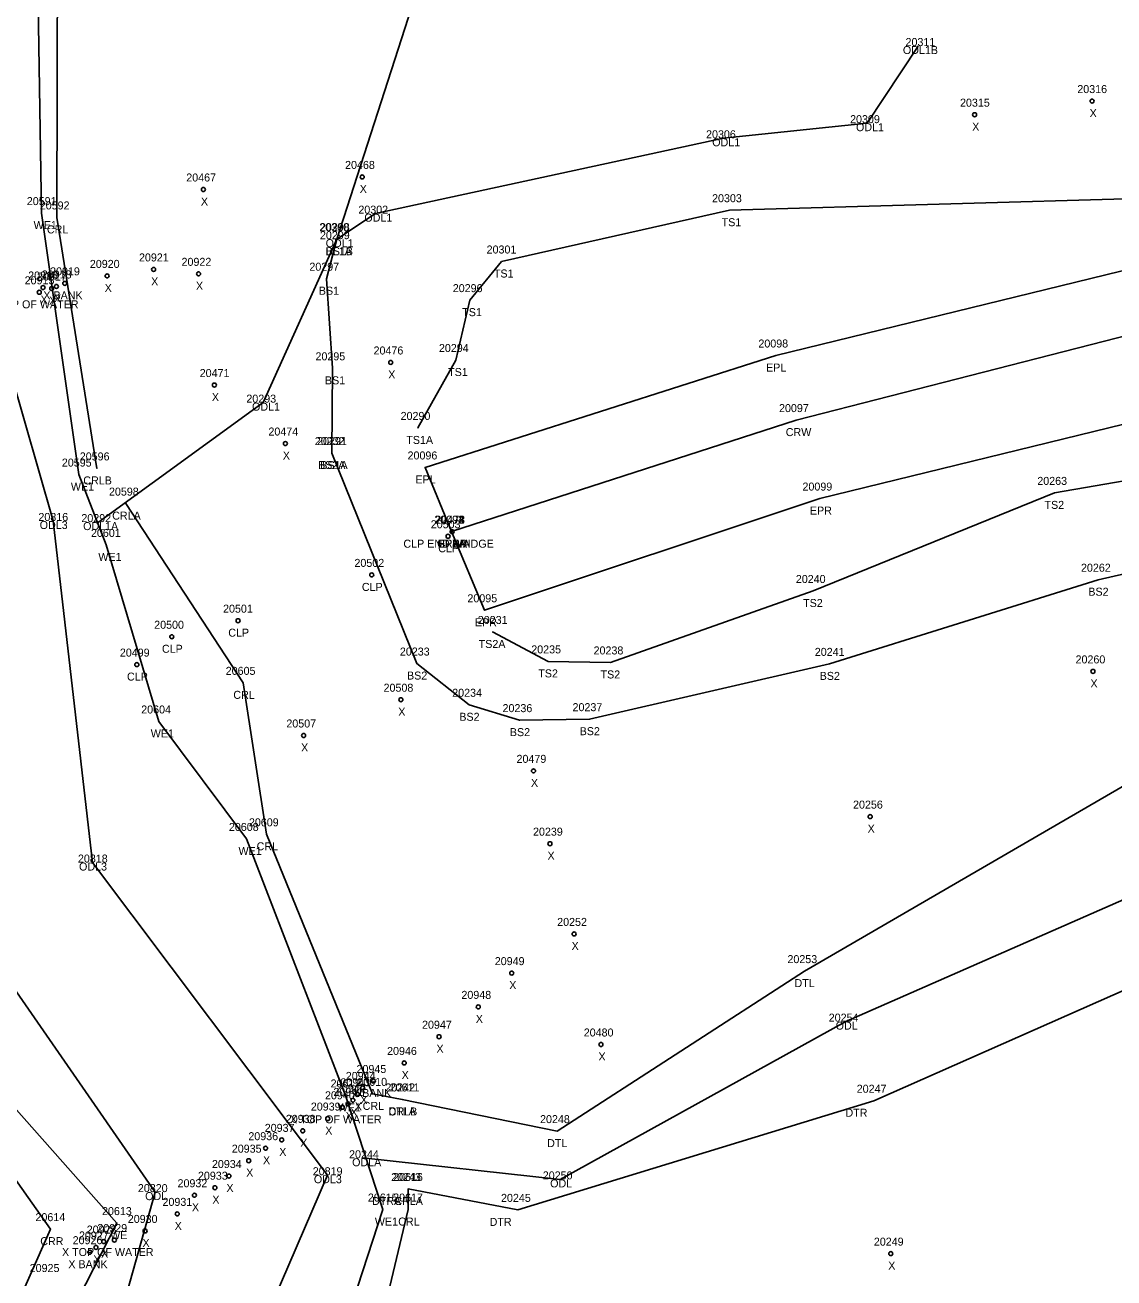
# Model space of a CAD drawing. Extents: x 1966740 to 1969291, y 1117378 to 1118461.
# Drawn here: x 1967825.7 to 1967961.8, y 1117802.2 to 1117958.8 of the extents above; entities that cross this region are included whole.
import ezdxf

# ---------------------------------------------------------------- set-up
doc = ezdxf.new("R2010")
doc.units = 0
for name, color, linetype in [('RD_DTM_BkLn1', 7, 'Continuous'), ('RD_DTM_BkLn2', 7, 'Continuous'), ('RD_EX_H2O', 7, 'Continuous'), ('RD_EX_H2O_txCode', 7, 'Continuous'), ('RD_EX_Road', 7, 'Continuous'), ('RD_EX_Road_txCode', 7, 'Continuous'), ('RD_SMD_Locator', 7, 'Continuous'), ('RD_SMD_Misc', 7, 'Continuous')]:
    doc.layers.add(name, color=color, linetype=linetype)

msp = doc.modelspace()

# ---------------------------------------------------------------- linework, layer by layer
at = {"layer": 'RD_DTM_BkLn1'}
for points in [[(1967864.65, 1117932.01), (1967874.44, 1117962.38), (1967900.7, 1118004.22), (1967938.17, 1118014.53)], [(1967878.98, 1117895.46), (1967922.07, 1117909.4), (1967968.89, 1117921.38), (1968013.49, 1117926.44), (1968059.29, 1117929.05), (1968105.63, 1117929.86), (1968159.12, 1117928.97), (1968212.65, 1117927.25), (1968318.5, 1117923.95), (1968422.42, 1117919.39), (1968529.36, 1117916.3)]]:
    msp.add_lwpolyline(points, dxfattribs=at)
at = {"layer": 'RD_DTM_BkLn2'}
for points in [[(1967874.77, 1117908.42), (1967879.51, 1117916.91), (1967881.27, 1117924.39), (1967885.24, 1117929.22), (1967913.7, 1117935.63), (1967966.11, 1117937.12), (1968012.39, 1117940.75), (1968059.42, 1117941.87), (1968105.44, 1117943.27), (1968158.32, 1117942.95), (1968212.48, 1117942.1), (1968371.25, 1117933.41), (1968422.85, 1117933.68), (1968531.49, 1117931.42)], [(1967864, 1117905.28), (1967864.09, 1117915.87), (1967863.33, 1117927.07), (1967864.65, 1117932.01)], [(1967884.1, 1117882.92), (1967891.06, 1117879.24), (1967898.84, 1117879.11), (1967924.17, 1117888.04), (1967954.33, 1117900.3), (1967970.81, 1117903.15), (1968012.93, 1117910.83), (1968059.62, 1117915.05), (1968105.25, 1117916.2), (1968157.57, 1117912.09), (1968210.74, 1117910.77), (1968320.32, 1117907.54), (1968423.18, 1117904.83), (1968528.99, 1117899.6)], [(1967864, 1117905.28), (1967874.64, 1117878.97), (1967881.18, 1117873.82), (1967887.49, 1117871.9), (1967896.22, 1117872.02), (1967926.22, 1117878.93), (1967959.79, 1117889.45), (1967973.08, 1117892.46), (1968014.67, 1117899.65), (1968058.49, 1117903.84)]]:
    msp.add_lwpolyline(points, dxfattribs=at)
at = {"layer": 'RD_EX_H2O'}
for points in [[(1967852.4, 1118390.04), (1967912.21, 1118383.64), (1967925.08, 1118336.82), (1967944.14, 1118294.4), (1967946.67, 1118243.15), (1967961.58, 1118191.28), (1967922.84, 1118148.62), (1967880.18, 1118117.11), (1967858.72, 1118073.64), (1967843.96, 1118030.69), (1967829.77, 1117984.65), (1967829.63, 1117934.73), (1967834.65, 1117903.36)], [(1967852.05, 1118385.41), (1967898.77, 1118376.41), (1967924.08, 1118337.23), (1967939.81, 1118294.93), (1967943.5, 1118242.16), (1967952.29, 1118191.75), (1967920.83, 1118149.81), (1967879.07, 1118118.61), (1967857.7, 1118074.04), (1967841.84, 1118031.93), (1967826.93, 1117984.9), (1967827.73, 1117935.27), (1967832.39, 1117902.59), (1967835.81, 1117893.8), (1967842.37, 1117871.73), (1967853.33, 1117857.05), (1967865.72, 1117824.99), (1967870.38, 1117810.73), (1967864.06, 1117791.33)], [(1967848.72, 1118350.07), (1967881.79, 1118342.06), (1967895.58, 1118338.92), (1967907.43, 1118282.36), (1967910.66, 1118232.56), (1967917.99, 1118192.64), (1967910.91, 1118176.45), (1967849.83, 1118135.18), (1967825.91, 1118086.77), (1967802.99, 1118041.98), (1967795.15, 1117992.28), (1967793.27, 1117935.35), (1967800.64, 1117889.8), (1967800.4, 1117872.52), (1967800.8, 1117854.99), (1967811.67, 1117837.73), (1967837.15, 1117809.04), (1967808.01, 1117752.12)], [(1967837.87, 1118086.59), (1967816.35, 1118042.52), (1967807.65, 1118000.54), (1967802.25, 1117964.95), (1967802.7, 1117929.05), (1967808.24, 1117891.66), (1967818.1, 1117847.27), (1967841.92, 1117812.91), (1967830.83, 1117773.47), (1967807.55, 1117730.13), (1967792.1, 1117688.21), (1967759.2, 1117626.42), (1967746.8, 1117597.58), (1967728.31, 1117575.82), (1967748.97, 1117519.79), (1967787.59, 1117491.86), (1967802.7, 1117484.72), (1967813.63, 1117479.24)], [(1967846.86, 1118079.71), (1967831.29, 1118034.88), (1967818.84, 1117997.76), (1967815.72, 1117964.67), (1967820.18, 1117928.06), (1967829.19, 1117896.79), (1967834.11, 1117854.1), (1967863.47, 1117815.02), (1967842.32, 1117765.95), (1967826.02, 1117725.1), (1967807.77, 1117682.35), (1967775.42, 1117611.81), (1967754.74, 1117587.12), (1967745.94, 1117565.65), (1967761.23, 1117525.28), (1967787.1, 1117502.15), (1967805.18, 1117494.11), (1967821.41, 1117490.36)], [(1967834.83, 1117896.65), (1967855.45, 1117911.58), (1967864.65, 1117932.01), (1967869.49, 1117935.2), (1967912.97, 1117944.62), (1967930.94, 1117946.51), (1967937.28, 1117956.15)], [(1967872.82, 1117824.49), (1967892.16, 1117820.53), (1967923.08, 1117840.53), (1967966.02, 1117865.44), (1967979.17, 1117870.44), (1968016.32, 1117890.41), (1968058.49, 1117903.84)], [(1967868.28, 1117817.14), (1967892.54, 1117814.5), (1967928.24, 1117834.22), (1967973.92, 1117854.29), (1967982.67, 1117861.15), (1968021.78, 1117883.3), (1968056.97, 1117897.44), (1968105.42, 1117898.77), (1968155.9, 1117899.84), (1968209.66, 1117898.76), (1968320.81, 1117895.57), (1968371.06, 1117895.25)], [(1967838.28, 1117898.96), (1967852.93, 1117876.56), (1967855.83, 1117857.63), (1967869.1, 1117825.19), (1967872.82, 1117824.49)], [(1967873.55, 1117813.3), (1967887.27, 1117810.69), (1967931.74, 1117824.33), (1967977.85, 1117844.69), (1967988.67, 1117850.69), (1968023.3, 1117871.08), (1968058.02, 1117883.74)], [(1967794.3, 1117875.45), (1967796.63, 1117853.43), (1967809.67, 1117835.4), (1967828.83, 1117808.28), (1967805.08, 1117754.56), (1967786.33, 1117708.04), (1967780.19, 1117689.35), (1967762.68, 1117651.19), (1967736.39, 1117616.3), (1967727.33, 1117611.21), (1967715.04, 1117573.35), (1967731.01, 1117514.73), (1967775.86, 1117468.11), (1967793.29, 1117458.88), (1967816.39, 1117454.18)], [(1967873.55, 1117813.3), (1967873.54, 1117810.73), (1967868.98, 1117791.48), (1967856.29, 1117756.05), (1967834.78, 1117721.72), (1967815.36, 1117678.52), (1967799.96, 1117628.39), (1967778.25, 1117587.63), (1967771.33, 1117582.11), (1967756.46, 1117564.6), (1967764.36, 1117543.85), (1967795.97, 1117517.33), (1967805.92, 1117513.21), (1967828.95, 1117503.56)]]:
    msp.add_lwpolyline(points, dxfattribs=at)
at = {"layer": 'RD_EX_Road'}
for points in [[(1967878.98, 1117895.46), (1967875.66, 1117903.48), (1967919.49, 1117917.47), (1967966.4, 1117928.95), (1968012.66, 1117935.42), (1968058.94, 1117938.37), (1968105.99, 1117939.39), (1968158.7, 1117938.56), (1968212.05, 1117937.21), (1968318.79, 1117933.28), (1968422.76, 1117929.93), (1968530.54, 1117925.7)], [(1967878.98, 1117895.46), (1967883.11, 1117885.63), (1967924.99, 1117899.59), (1967970.68, 1117910.78), (1968014.42, 1117916.56), (1968059.13, 1117919.49), (1968105.39, 1117920.31), (1968159.16, 1117919.37), (1968212.5, 1117917.97), (1968317.55, 1117914.44), (1968421.52, 1117910.75), (1968527.82, 1117906.41)]]:
    msp.add_lwpolyline(points, dxfattribs=at)
at = {"layer": 'RD_SMD_Locator'}
for centre, radius in [((1967937.28, 1117956.15), 0.001), ((1967959.04, 1117949.27), 0.25), ((1967944.36, 1117947.57), 0.25), ((1967930.94, 1117946.51), 0.001), ((1967912.97, 1117944.62), 0.001), ((1967867.81, 1117939.79), 0.25), ((1967847.96, 1117938.22), 0.25), ((1967827.73, 1117935.27), 0.001), ((1967829.63, 1117934.73), 0.001), ((1967869.49, 1117935.2), 0.001), ((1967913.7, 1117935.63), 0.001), ((1967864.65, 1117932.01), 0.001), ((1967864.65, 1117932.01), 0.001), ((1967864.65, 1117932.01), 0.001), ((1967841.74, 1117928.23), 0.25), ((1967885.24, 1117929.22), 0.001), ((1967830.64, 1117926.49), 0.25), ((1967835.93, 1117927.42), 0.25), ((1967847.35, 1117927.68), 0.25), ((1967863.33, 1117927.07), 0.001), ((1967827.45, 1117925.37), 0.25), ((1967827.92, 1117925.97), 0.25), ((1967829, 1117925.84), 0.25), ((1967829.59, 1117926.1), 0.25), ((1967881.27, 1117924.39), 0.001), ((1967919.49, 1117917.47), 0.001), ((1967864.09, 1117915.87), 0.001), ((1967871.37, 1117916.6), 0.25), ((1967879.51, 1117916.91), 0.001), ((1967849.33, 1117913.78), 0.25), ((1967855.45, 1117911.58), 0.001), ((1967922.07, 1117909.4), 0.001), ((1967874.77, 1117908.42), 0.001), ((1967858.21, 1117906.47), 0.25), ((1967864, 1117905.28), 0.001), ((1967864, 1117905.28), 0.001), ((1967834.65, 1117903.36), 0.001), ((1967875.66, 1117903.48), 0.001), ((1967832.39, 1117902.59), 0.001), ((1967954.33, 1117900.3), 0.001), ((1967838.28, 1117898.96), 0.001), ((1967924.99, 1117899.59), 0.001), ((1967829.19, 1117896.79), 0.001), ((1967834.83, 1117896.65), 0.001), ((1967878.54, 1117894.88), 0.25), ((1967879.05, 1117895.45), 0.25), ((1967878.98, 1117895.46), 0.001), ((1967878.98, 1117895.46), 0.001), ((1967878.98, 1117895.46), 0.001), ((1967835.81, 1117893.8), 0.001), ((1967869, 1117890.05), 0.25), ((1967959.79, 1117889.45), 0.001), ((1967924.17, 1117888.04), 0.001), ((1967852.29, 1117884.33), 0.25), ((1967883.11, 1117885.63), 0.001), ((1967884.1, 1117882.92), 0.001), ((1967844.01, 1117882.32), 0.25), ((1967839.64, 1117878.84), 0.25), ((1967874.64, 1117878.97), 0.001), ((1967891.06, 1117879.24), 0.001), ((1967898.84, 1117879.11), 0.001), ((1967926.22, 1117878.93), 0.001), ((1967959.15, 1117877.99), 0.25), ((1967852.93, 1117876.56), 0.001), ((1967872.64, 1117874.45), 0.25), ((1967881.18, 1117873.82), 0.001), ((1967842.37, 1117871.73), 0.001), ((1967887.49, 1117871.9), 0.001), ((1967896.22, 1117872.02), 0.001), ((1967860.49, 1117869.98), 0.25), ((1967889.22, 1117865.56), 0.25), ((1967931.3, 1117859.84), 0.25), ((1967855.83, 1117857.63), 0.001), ((1967853.33, 1117857.05), 0.001), ((1967891.28, 1117856.46), 0.25), ((1967834.11, 1117854.1), 0.001), ((1967894.3, 1117845.18), 0.25), ((1967886.5, 1117840.28), 0.25), ((1967923.08, 1117840.53), 0.001), ((1967882.32, 1117836.06), 0.25), ((1967928.24, 1117834.22), 0.001), ((1967877.41, 1117832.33), 0.25), ((1967897.65, 1117831.36), 0.25), ((1967873.06, 1117829.05), 0.25), ((1967869.21, 1117826.8), 0.25), ((1967865.72, 1117824.99), 0.001), ((1967867.2, 1117825.13), 0.25), ((1967867.88, 1117825.93), 0.25), ((1967869.1, 1117825.19), 0.001), ((1967865.32, 1117823.51), 0.25), ((1967866.04, 1117823.93), 0.25), ((1967866.64, 1117824.4), 0.25), ((1967872.82, 1117824.49), 0.001), ((1967872.82, 1117824.49), 0.001), ((1967931.74, 1117824.33), 0.001), ((1967863.5, 1117822.1), 0.25), ((1967860.38, 1117820.57), 0.25), ((1967892.16, 1117820.53), 0.001), ((1967855.73, 1117818.4), 0.25), ((1967857.75, 1117819.44), 0.25), ((1967853.62, 1117816.84), 0.25), ((1967868.28, 1117817.14), 0.001), ((1967849.4, 1117813.46), 0.25), ((1967851.15, 1117814.92), 0.25), ((1967863.47, 1117815.02), 0.001), ((1967892.54, 1117814.5), 0.001), ((1967841.92, 1117812.91), 0.001), ((1967846.84, 1117812.52), 0.25), ((1967873.55, 1117813.3), 0.001), ((1967873.55, 1117813.3), 0.001), ((1967870.38, 1117810.73), 0.001), ((1967873.54, 1117810.73), 0.001), ((1967887.27, 1117810.69), 0.001), ((1967837.15, 1117809.04), 0.001), ((1967844.69, 1117810.19), 0.25), ((1967828.83, 1117808.28), 0.001), ((1967840.67, 1117808.06), 0.25), ((1967834.53, 1117805.99), 0.25), ((1967835.5, 1117806.73), 0.25), ((1967836.83, 1117806.92), 0.25), ((1967833.76, 1117805.4), 0.25), ((1967933.88, 1117805.22), 0.25)]:
    msp.add_circle(centre, radius, dxfattribs=at)

# ---------------------------------------------------------------- texts
at = {"layer": 'RD_EX_H2O_txCode'}
for s, p in [('20311', (1967935.72, 1117956.15)), ('ODL1B', (1967935.39, 1117955.15)), ('20309', (1967928.79, 1117946.51)), ('20306', (1967910.79, 1117944.62)), ('ODL1', (1967929.53, 1117945.51)), ('ODL1', (1967911.56, 1117943.62)), ('20591', (1967825.89, 1117936.27)), ('20592', (1967827.51, 1117935.73)), ('20302', (1967867.33, 1117935.2)), ('ODL1', (1967868.08, 1117934.2)), ('WE1', (1967826.74, 1117933.27)), ('CRL', (1967828.4, 1117932.73)), ('20299', (1967862.53, 1117932.01)), ('ODL1', (1967863.24, 1117931.01)), ('20293', (1967853.33, 1117911.58)), ('ODL1', (1967854.04, 1117910.58)), ('20595', (1967830.27, 1117903.59)), ('20596', (1967832.51, 1117904.36)), ('WE1', (1967831.4, 1117900.59)), ('CRLB', (1967832.95, 1117901.36)), ('20598', (1967836.16, 1117899.96)), ('20816', (1967827.34, 1117896.79)), ('ODL3', (1967827.5, 1117895.79)), ('20292', (1967832.71, 1117896.65)), ('CRLA', (1967836.56, 1117896.96)), ('ODL1A', (1967832.93, 1117895.65)), ('20601', (1967833.91, 1117894.8)), ('WE1', (1967834.83, 1117891.8)), ('20605', (1967850.75, 1117877.56)), ('CRL', (1967851.7, 1117874.56)), ('20604', (1967840.19, 1117872.73)), ('WE1', (1967841.38, 1117869.73)), ('20609', (1967853.65, 1117858.63)), ('20608', (1967851.15, 1117858.05)), ('WE1', (1967852.35, 1117855.05)), ('CRL', (1967854.61, 1117855.63)), ('20818', (1967832.28, 1117854.1)), ('ODL3', (1967832.42, 1117853.1)), ('20253', (1967920.96, 1117841.53)), ('DTL', (1967921.84, 1117838.53)), ('20254', (1967926.12, 1117834.22)), ('ODL', (1967926.99, 1117833.22)), ('20612', (1967863.86, 1117825.99)), ('20610', (1967867.2, 1117826.19)), ('20242', (1967870.7, 1117825.49)), ('20611', (1967871.25, 1117825.49)), ('20247', (1967929.62, 1117825.33)), ('WE1', (1967864.74, 1117822.99)), ('CRL', (1967867.87, 1117823.19)), ('CRLB', (1967871.12, 1117822.49)), ('DTLA', (1967871.09, 1117822.49)), ('DTR', (1967928.21, 1117822.33)), ('20248', (1967890.04, 1117821.53)), ('DTL', (1967890.92, 1117818.53)), ('20244', (1967866.17, 1117817.14)), ('ODLA', (1967866.55, 1117816.14)), ('20819', (1967861.63, 1117815.02)), ('20243', (1967871.43, 1117814.3)), ('20616', (1967871.67, 1117814.3)), ('20250', (1967890.38, 1117814.5)), ('20820', (1967839.77, 1117812.91)), ('ODL3', (1967861.77, 1117814.02)), ('ODL', (1967891.3, 1117813.5)), ('ODL', (1967840.68, 1117811.91)), ('20615', (1967868.52, 1117811.73)), ('DTRA', (1967869.04, 1117811.3)), ('20617', (1967871.68, 1117811.73)), ('CRLA', (1967871.83, 1117811.3)), ('20245', (1967885.16, 1117811.69)), ('20613', (1967835.29, 1117810.04)), ('20614', (1967826.97, 1117809.28)), ('WE1', (1967869.39, 1117808.73)), ('CRL', (1967872.31, 1117808.73)), ('DTR', (1967883.74, 1117808.69)), ('WE', (1967836.31, 1117807.04)), ('CRR', (1967827.57, 1117806.28))]:
    msp.add_text(s, height=1, dxfattribs=at).set_placement(p)
at = {"layer": 'RD_EX_Road_txCode'}
for s, p in [('20098', (1967917.33, 1117918.47)), ('EPL', (1967918.29, 1117915.47)), ('20096', (1967873.48, 1117904.48)), ('EPL', (1967874.46, 1117901.48)), ('20099', (1967922.84, 1117900.59)), ('EPR', (1967923.77, 1117897.59)), ('20093', (1967876.82, 1117896.46)), ('20094', (1967876.82, 1117896.46)), ('EPRA', (1967877.27, 1117893.46)), ('EPLA', (1967877.29, 1117893.46)), ('20095', (1967880.96, 1117886.63)), ('EPR', (1967881.89, 1117883.63))]:
    msp.add_text(s, height=1, dxfattribs=at).set_placement(p)
at = {"layer": 'RD_SMD_Misc'}
for s, p in [('20316', (1967957.19, 1117950.27)), ('20315', (1967942.53, 1117948.57)), ('X', (1967958.73, 1117947.27)), ('X', (1967944.05, 1117945.57)), ('20468', (1967865.67, 1117940.79)), ('20467', (1967845.82, 1117939.22)), ('X', (1967867.5, 1117937.79)), ('20303', (1967911.54, 1117936.63)), ('X', (1967847.65, 1117936.22)), ('TS1', (1967912.74, 1117933.63)), ('20300', (1967862.45, 1117933.01)), ('20298', (1967862.53, 1117933.01)), ('20301', (1967883.36, 1117930.22)), ('20921', (1967839.91, 1117929.23)), ('20922', (1967845.23, 1117928.68)), ('BS1B', (1967863.23, 1117930.01)), ('BL1A', (1967863.24, 1117930.01)), ('20918', (1967827.76, 1117927.1)), ('20919', (1967828.8, 1117927.49)), ('20920', (1967833.77, 1117928.42)), ('20297', (1967861.21, 1117928.07)), ('TS1', (1967884.27, 1117927.22)), ('20915', (1967825.62, 1117926.37)), ('20916', (1967826.06, 1117926.97)), ('20917', (1967827.16, 1117926.84)), ('X', (1967841.43, 1117926.23)), ('X', (1967847.03, 1117925.68)), ('X', (1967827.6, 1117923.97)), ('X BANK', (1967827.96, 1117924.49)), ('X', (1967829.28, 1117924.1)), ('X', (1967835.62, 1117925.42)), ('BS1', (1967862.39, 1117925.07)), ('20296', (1967879.13, 1117925.39)), ('X TOP OF WATER', (1967820.91, 1117923.37)), ('X', (1967828.68, 1117923.84)), ('TS1', (1967880.31, 1117922.39)), ('20294', (1967877.4, 1117917.91)), ('20295', (1967861.97, 1117916.87)), ('20476', (1967869.23, 1117917.6)), ('20471', (1967847.5, 1117914.78)), ('X', (1967871.06, 1117914.6)), ('TS1', (1967878.55, 1117914.91)), ('BS1', (1967863.15, 1117913.87)), ('X', (1967849.02, 1117911.78)), ('20097', (1967919.91, 1117910.4)), ('20290', (1967872.61, 1117909.42)), ('20474', (1967856.09, 1117907.47)), ('CRW', (1967920.75, 1117907.4)), ('20232', (1967861.89, 1117906.28)), ('20291', (1967862.17, 1117906.28)), ('TS1A', (1967873.32, 1117906.42)), ('X', (1967857.89, 1117904.47)), ('BS2A', (1967862.29, 1117903.28)), ('BS1A', (1967862.57, 1117903.28)), ('20263', (1967952.19, 1117901.3)), ('TS2', (1967953.09, 1117898.3)), ('20503', (1967876.38, 1117895.88)), ('20092', (1967876.82, 1117896.46)), ('20478', (1967876.94, 1117896.45)), ('CLP END BRIDGE', (1967872.96, 1117893.45)), ('CRWA', (1967877.18, 1117893.46)), ('CLP', (1967877.31, 1117892.88)), ('20502', (1967866.84, 1117891.05)), ('20262', (1967957.65, 1117890.45)), ('CLP', (1967867.77, 1117888.05)), ('20240', (1967922.01, 1117889.04)), ('BS2', (1967958.57, 1117887.45)), ('20501', (1967850.42, 1117885.33)), ('TS2', (1967922.92, 1117886.04)), ('20500', (1967841.81, 1117883.32)), ('20231', (1967882.26, 1117883.92)), ('CLP', (1967851.07, 1117882.33)), ('CLP', (1967842.78, 1117880.32)), ('TS2A', (1967882.37, 1117880.92)), ('20235', (1967888.94, 1117880.24)), ('20238', (1967896.73, 1117880.11)), ('20499', (1967837.52, 1117879.84)), ('20233', (1967872.52, 1117879.97)), ('20241', (1967924.38, 1117879.93)), ('20260', (1967956.97, 1117878.99)), ('BS2', (1967873.41, 1117876.97)), ('TS2', (1967889.82, 1117877.24)), ('TS2', (1967897.6, 1117877.11)), ('BS2', (1967924.99, 1117876.93)), ('CLP', (1967838.41, 1117876.84)), ('20508', (1967870.48, 1117875.45)), ('X', (1967958.83, 1117875.99)), ('20234', (1967879.06, 1117874.82)), ('X', (1967872.32, 1117872.45)), ('20236', (1967885.35, 1117872.9)), ('20237', (1967894.1, 1117873.02)), ('20507', (1967858.33, 1117870.98)), ('BS2', (1967879.95, 1117871.82)), ('BS2', (1967886.26, 1117869.9)), ('BS2', (1967894.99, 1117870.02)), ('X', (1967860.17, 1117867.98)), ('20479', (1967887.1, 1117866.56)), ('X', (1967888.9, 1117863.56)), ('20256', (1967929.16, 1117860.84)), ('20239', (1967889.16, 1117857.46)), ('X', (1967930.98, 1117857.84)), ('X', (1967890.97, 1117854.46)), ('20252', (1967892.18, 1117846.18)), ('X', (1967893.98, 1117843.18)), ('20949', (1967884.38, 1117841.28)), ('X', (1967886.19, 1117838.28)), ('20948', (1967880.21, 1117837.06)), ('20947', (1967875.29, 1117833.33)), ('X', (1967882.01, 1117834.06)), ('20480', (1967895.5, 1117832.36)), ('20946', (1967870.92, 1117830.05)), ('X', (1967877.09, 1117830.33)), ('X', (1967897.34, 1117829.36)), ('20944', (1967865.76, 1117826.93)), ('20945', (1967867.1, 1117827.8)), ('X', (1967872.74, 1117827.05)), ('20942', (1967864.52, 1117825.4)), ('20943', (1967865.08, 1117826.13)), ('20940', (1967863.16, 1117824.51)), ('20941', (1967864.21, 1117824.93)), ('X BANK', (1967866.54, 1117824.8)), ('X', (1967867.57, 1117823.93)), ('20939', (1967861.39, 1117823.1)), ('X', (1967866.33, 1117822.4)), ('X', (1967866.89, 1117823.13)), ('20938', (1967858.26, 1117821.57)), ('X TOP OF WATER', (1967858.79, 1117821.51)), ('X', (1967865.73, 1117821.93)), ('20936', (1967853.58, 1117819.4)), ('20937', (1967855.63, 1117820.44)), ('X', (1967863.19, 1117820.1)), ('20935', (1967851.51, 1117817.84)), ('X', (1967857.44, 1117817.44)), ('X', (1967860.06, 1117818.57)), ('20934', (1967849.03, 1117815.92)), ('X', (1967855.41, 1117816.4)), ('20933', (1967847.28, 1117814.46)), ('X', (1967853.31, 1117814.84)), ('20932', (1967844.73, 1117813.52)), ('X', (1967850.84, 1117812.92)), ('20931', (1967842.85, 1117811.19)), ('X', (1967849.08, 1117811.46)), ('X', (1967846.53, 1117810.52)), ('20930', (1967838.51, 1117809.06)), ('X', (1967844.37, 1117808.19)), ('20927', (1967832.41, 1117806.99)), ('20928', (1967833.38, 1117807.73)), ('20929', (1967834.71, 1117807.92)), ('X TOP OF WATER', (1967830.29, 1117804.92)), ('20926', (1967831.62, 1117806.4)), ('X', (1967840.35, 1117806.06)), ('20249', (1967931.76, 1117806.22)), ('X BANK', (1967831.08, 1117803.4)), ('X', (1967834.21, 1117803.99)), ('X', (1967835.18, 1117804.73)), ('20925', (1967826.25, 1117802.92)), ('X', (1967933.56, 1117803.22))]:
    msp.add_text(s, height=1, dxfattribs=at).set_placement(p)

doc.saveas('drawing.dxf')
